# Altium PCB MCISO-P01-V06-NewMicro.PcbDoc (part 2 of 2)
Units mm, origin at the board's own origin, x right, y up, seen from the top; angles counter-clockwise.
Board outline 60 x 112.78 mm, 2 copper layers (Top Layer, Bottom Layer), stack 1.57 mm thick; 124 components, 85 nets, 520 pads, 108 vias.
Unrouted connection lines stored in the file: 6.
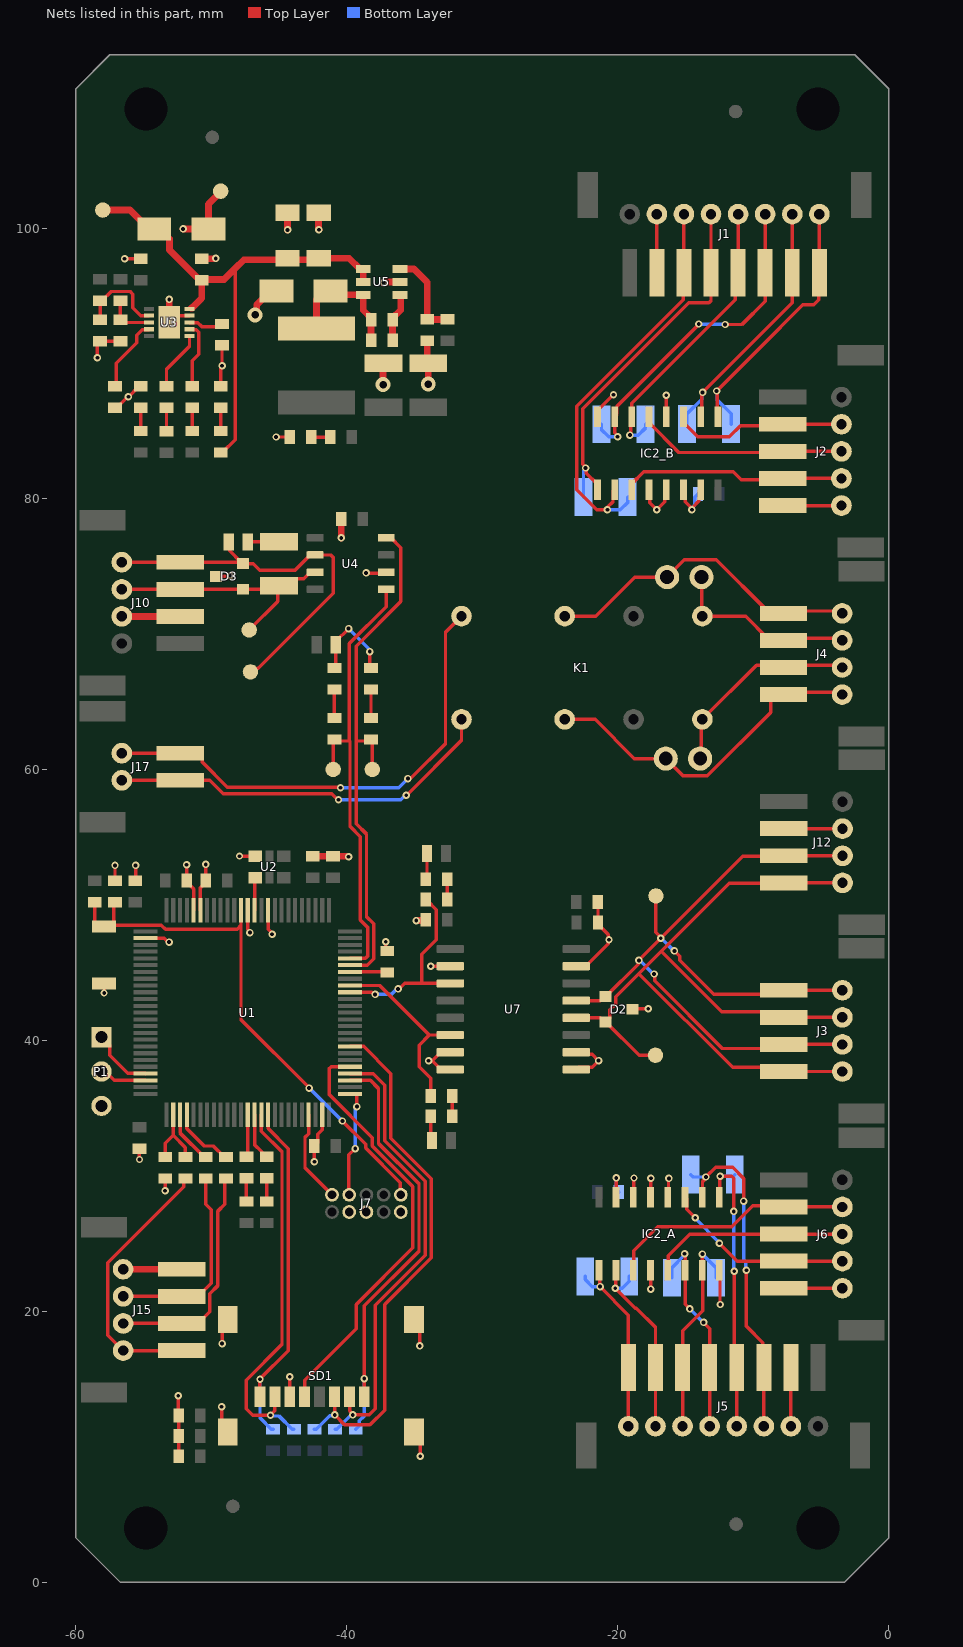
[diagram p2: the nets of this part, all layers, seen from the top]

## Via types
v1: diameter 0.55, hole 0.279, Top Layer to Bottom Layer, 100 vias
v2: diameter 1.1, hole 0.56, Top Layer to Bottom Layer, 3 vias
v3: diameter 0.508, hole 0.279, Top Layer to Bottom Layer, 3 vias
v4: diameter 1.092, hole 0.559, Top Layer to Bottom Layer, 2 vias

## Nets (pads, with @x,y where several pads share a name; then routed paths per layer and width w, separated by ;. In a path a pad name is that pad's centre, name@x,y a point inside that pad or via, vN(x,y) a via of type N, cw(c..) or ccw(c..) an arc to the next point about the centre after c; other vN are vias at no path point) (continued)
12VP: C11.2 C18.1 C21.1 D1.K R14.2 TP2.1 U3.10 U5.4 U5.5 | length 40.3
  Top Layer w0.254: U3.10@-51.611,94.026 U3.10@-51.517,94.026 ; R14.2@-49.311,83.426 -49.184,83.426 -48.239,84.371 -48.239,97.008
  Top Layer w0.5: TP2.1@-58.011,101.326 -56.011,101.326 -54.611,99.926 D1.K@-54.211,99.926 -53.811,99.926 -53.088,99.203 -53.088,98.383 -50.711,96.006 -50.711,94.808 -51.415,94.104 U3.10@-51.486,94.104 ; C11.2@-50.711,96.133 -50.652,96.192 -49.055,96.192 -48.239,97.008 -47.59,97.657 -42.188,97.657 C18.1@-42.079,97.765 -39.834,97.765 -39.035,96.967 U5.4@-38.785,96.967 U5.5@-38.785,96.017
BOOT: R1.1 U1.94 | length 2.8
  Top Layer w0.254: U1.94@-39.761,45.076 -37.054,45.076 R1.1@-37.011,45.033
"CAN GLV RX": R25.1 TP9.1 U1.95 U4.4 | length 39
  Top Layer w0.254: U1.95@-39.761,45.576 -38.48,45.576 -38.014,46.042 -38.014,48.63 -38.544,49.159 -38.544,55.259 -39.311,56.026 -39.311,62.126 ; TP9.1@-38.111,60.026 -38.111,62.133 R25.1@-38.211,62.233 -38.318,62.126 -39.311,62.126 ; U4.4@-37.086,77.131 -36.736,77.131 -36.011,76.406 -36.011,72.426 -39.311,69.126 -39.311,62.926 -39.311,62.126
"CAN GLX TX": R24.1 TP11.1 U1.96 U4.1 | length 33.5
  Top Layer w0.254: TP11.1@-41.011,60.026 -41.011,62.133 R24.1@-40.911,62.233 -40.804,62.126 -39.811,62.126 ; U1.96@-39.761,46.076 -39.738,46.099 -38.617,46.099 -38.468,46.248 -38.468,48.384 -38.998,48.913 -38.998,55.071 -39.765,55.838 -39.765,62.08 -39.811,62.126 ; U4.1@-37.086,73.321 -37.086,72.051 -39.811,69.326 -39.811,62.126
"CAN H": D3.2 J10.4 J14.1 TP8.1 U4.6 | length 29.4
  Top Layer w0.254: J10.4@-56.611,75.326 J10.4@-52.282,75.326 D3.2@-47.811,75.326 ; J14.1@-48.708,76.826 -48.653,76.771 -48.653,76.168 D3.2@-47.811,75.326 ; D3.2@-47.661,75.226 -46.911,75.226 -46.411,74.726 -43.821,74.726 -42.686,75.861 U4.6@-42.336,75.861 -41.195,75.861 -41.011,75.677 -41.011,73.026 -46.541,67.496 -46.601,67.496 -46.87,67.226 TP8.1@-47.111,67.226 ; D3.2@-47.661,75.326 D3.2@-47.811,75.326
"CAN HV RX": R22.1 U1.91 U7.3 | length 14.7
  Top Layer w0.254: U1.91@-39.761,43.576 -38.147,43.576 -37.991,43.42 v1(-37.911,43.42) ; v1(-36.211,43.826) -36.131,43.826 -35.726,44.231 -34.425,44.231 ; R22.1@-34.08,50.371 -33.393,49.684 -33.393,47.44 -34.454,46.379 -34.454,44.261 -34.425,44.231 ; U7.3@-32.361,44.231 -34.425,44.231
  Bottom Layer w0.254: v1(-37.911,43.42) -36.697,43.42 -36.291,43.826 v1(-36.211,43.826)
"CAN HV TX": R21.1 U1.92 U7.6 | length 14.1
  Top Layer w0.254: U1.92@-39.761,44.076 -37.561,44.076 -33.906,40.421 ; R21.1@-33.804,35.926 -33.804,37.221 -34.662,38.079 -34.662,39.665 -33.906,40.421 ; U7.6@-32.361,40.421 -33.906,40.421
"CAN L": D3.1 J10.3 R26.1 TP10.1 U4.7 | length 18.6
  Top Layer w0.254: J10.3@-56.611,73.326 J10.3@-52.282,73.326 -47.911,73.326 D3.1@-47.661,73.326 -45.036,73.326 -45.111,73.252 -45.111,72.426 TP10.1@-47.211,70.326 ; R26.1@-45.011,73.575 -44.488,74.098 -43.179,74.098 -42.686,74.591 U4.7@-42.336,74.591
"CAN MAIN LED": DS9.1 DS10.1 J13.2 | length 7
  Top Layer w0.254: DS9.1@-40.911,67.52 -40.814,67.617 J13.2@-40.814,69.226 -40.814,69.48 v1(-39.868,70.426) v1@-39.811,70.426 ; v1(-38.311,68.726) -38.311,67.62 DS10.1@-38.211,67.52
  Bottom Layer w0.254: v1(-39.868,70.426) -38.311,68.869 v1(-38.311,68.726)
"CAN MAIN RX LED": DS10.2 R25.2 | length 2.1
  Top Layer w0.254: R25.2@-38.211,63.82 DS10.2@-38.211,65.933
"CAN MAIN TX LED": DS9.2 R24.2 | length 2.1
  Top Layer w0.254: R24.2@-40.911,63.82 DS9.2@-40.911,65.933
"CAN RX LED": DS8.2 R22.2 | length 1.4
  Top Layer w0.254: R22.2@-32.586,50.423 -32.586,51.757 DS8.2@-32.518,51.826
"CAN TX LED": DS7.2 R21.2 | length 1.5
  Top Layer w0.254: DS7.2@-32.218,34.426 R21.2@-32.218,35.926
CLMODE: R15.2 U3.4 | length 5.6
  Top Layer w0.254: R15.2@-57.011,88.226 -57.011,90.019 -55.511,91.519 -55.511,92.082 -55.09,92.503 -54.634,92.503 U3.4@-54.611,92.526
"COM A": J4.4 J8.1 K1.13 | length 25.4
  Top Layer w0.254: K1.13@-23.911,63.726 -21.665,63.726 -18.765,60.826 J8.1@-16.451,60.826 -15.181,59.556 -13.385,59.556 -8.711,64.23 -8.711,65.303 -8.288,65.726 -7.74,65.726 J4.4@-3.411,65.726
"COM B": J4.1 J9.2 K1.4 | length 23.8
  Top Layer w0.254: K1.4@-23.911,71.346 -21.605,71.346 -18.725,74.226 J9.2@-16.351,74.226 -15.081,75.496 -12.71,75.496 -8.94,71.726 -7.74,71.726 J4.1@-3.411,71.726
FLAG: DS4.2 U3.6 | length 4.4
  Top Layer w0.254: DS4.2@-53.311,88.313 -53.311,89.559 -51.611,91.259 U3.6@-51.611,92.026
GND: C1.1 C2.1 C3.1 C4.1 C5.1 C6.2 C7.1 C8.1 C9.1 C10.1 C11.1 C12.1 C15.2 C18.2 C19.1 C21.2 C22.1 C23.1 C24.1 D1.A D3.3 D4.A DS5.2 DS6.2 DS11.2 J7.3 J7.5 J7.9 J10.2 J15.4 P1.3 R1.2 R8.1 R15.1 R16.1 R17.1 R18.1 R29.1 SD1.6 SD1.9 SD1.10 SD1.11 SD1.12 SW1.1 TP3.1 U1.10 U1.13 U1.20 U1.21 U1.27 U1.74 U2.3 U3.9 U3.11 U4.2 U5.2 U7.2 U7.7 U7.8 | length 89.3
  Top Layer w0.254: v1(-58.411,90.426) -58.411,91.439 R16.1@-58.211,91.639 R17.1@-56.711,91.639 ; v3(-57.911,43.526) SW1.1@-57.911,44.326 ; R15.1@-57.124,86.72 R15.1@-57.111,86.733 ; C7.1@-57.111,51.82 v1(-57.112,52.944) ; R15.1@-57.011,86.639 -57.011,86.706 -56.177,87.54 -56.111,87.54 -55.338,88.313 DS5.2@-55.211,88.313 ; v1(-56.405,97.737) -55.229,97.737 C12.1@-55.211,97.72 ; C3.1@-55.611,51.82 -55.59,51.84 v1(-55.59,52.942) ; v3(-55.311,31.226) C4.1@-55.311,32.033 ; U1.27@-54.861,47.576 -53.492,47.576 -53.198,47.282 v1(-53.118,47.282) ; v1(-53.411,28.926) R8.1@-53.411,29.826 ; U3.11@-53.111,93.026 -52.611,93.526 U3.9@-51.611,93.526 ; v1(-52.439,13.792) -52.439,12.348 C10.1@-52.417,12.326 C9.1@-52.417,10.826 C8.1@-52.417,9.326 ; v1(-51.824,52.984) -51.824,51.839 C5.1@-51.811,51.826 -51.811,51.699 -51.311,51.199 U1.21@-51.311,49.626 ; U1.20@-50.811,49.626 -50.803,49.634 -50.803,51.301 -50.404,51.699 C24.1@-50.404,51.826 -50.411,51.832 v1(-50.411,53.015) ; D3.3@-49.661,74.276 -48.674,74.276 -48.624,74.326 v1(-48.611,74.326) ; DS6.2@-49.311,88.313 -49.311,89.646 -49.211,89.746 R18.1@-49.211,91.333 ; v1(-49.241,12.984) -49.241,11.576 SD1.9@-48.791,11.126 ; v1(-49.204,17.637) -49.204,19.013 SD1.10@-48.791,19.426 ; v3(-47.911,53.626) U2.3@-46.761,53.626 ; U1.13@-47.311,49.626 -47.311,48.223 -47.155,48.067 v1(-47.155,47.986) ; U1.10@-45.811,49.626 -45.811,48.238 -45.517,47.944 v1(-45.517,47.864) ; v1(-45.22,84.571) -44.221,84.571 DS11.2@-44.212,84.562 ; v1(-44.212,15.192) -44.212,13.727 SD1.6@-44.211,13.726 ; v1(-42.392,31.065) -42.392,32.221 C1.1@-42.398,32.226 -42.144,32.48 -42.144,33.093 -41.82,33.417 -41.82,34.517 U1.74@-41.811,34.526 ; v1@-38.558,74.499 -37.178,74.499 U4.2@-37.086,74.591 ; v1(-37.128,47.309) -37.128,46.737 R1.2@-37.011,46.62 ; SD1.12@-35.041,11.126 -34.583,10.668 v1(-34.583,9.321) ; SD1.11@-35.041,19.426 -34.618,19.003 v1(-34.618,17.468) ; v1(-33.963,38.515) v1@-33.697,38.515 ; v1(-33.798,45.503) v1(-33.798,45.503) -32.362,45.502 U7.2@-32.361,45.501 ; U7.8@-32.361,37.881 -33.061,37.881 -33.695,38.515 v1@-33.697,38.515 ; U7.7@-32.361,39.151 -33.061,39.151 v1@-33.697,38.515
  Top Layer w0.5: J10.2@-56.611,71.326 J10.2@-52.282,71.326 ; J15.4@-56.511,23.126 J15.4@-52.182,23.126 ; U3.11@-53.111,93.026 v1(-53.111,94.726) ; v1(-52.088,99.929) -50.214,99.929 D1.A@-50.211,99.926 -50.211,101.757 -49.311,102.657 TP3.1@-49.311,102.726 ; C11.1@-50.711,97.72 -50.708,97.723 -49.724,97.723 -49.693,97.754 v1(-49.679,97.754) ; v2(-46.765,93.584) -46.651,93.699 -46.651,94.307 -45.599,95.358 D4.A@-45.199,95.358 ; C21.2@-44.379,101.122 -44.374,101.117 v1(-44.374,99.855) ; C6.2@-42.511,53.62 -39.924,53.62 -39.885,53.58 v1(-39.871,53.58) ; C18.2@-42.079,101.122 -42.079,99.9 -42.058,99.879 v1(-42.058,99.865) ; v1(-40.404,77.124) C15.2@-40.404,78.526 ; v2(-37.318,88.442) -37.318,89.994 C22.1@-37.303,90.009 ; v1(-37.284,95.968) -37.27,95.968 -37.222,96.017 U5.2@-36.085,96.017 ; v1(-34.871,48.865) -34.862,48.875 -34.222,48.875 C23.1@-34.173,48.923 ; R29.1@-34.066,91.669 -34.066,90.103 C19.1@-33.988,90.024 -33.984,90.02 v2(-33.984,88.47)
  other v1: -38.576,74.532 -56.125,87.54 -49.211,89.826
"GND INV A": C20_B.1 IC2_B.4 IC2_B.8 IC2_B.12 IC2_B.13 IC2_B.14 IC2_B.15 J1.2 J2.5 | length 20
  Top Layer w0.254: IC2_B.8@-21.52,86.498 -20.324,87.694 v1(-20.311,87.694) ; IC2_B.12@-17.71,80.673 -17.634,80.598 -17.634,79.724 v1(-17.109,79.198) -16.525,79.782 -16.525,80.588 IC2_B.13@-16.44,80.673 ; J1.2@-17.111,96.686 J1.2@-17.111,101.026 ; IC2_B.4@-16.44,86.073 -16.425,86.088 -16.425,87.632 v1(-16.41,87.647) ; IC2_B.14@-15.17,80.673 -15.022,80.525 -15.022,79.794 -14.58,79.353 -14.58,79.335 -14.542,79.296 -14.506,79.296 -14.467,79.335 -14.467,79.397 -13.998,79.866 -13.998,80.575 IC2_B.15@-13.9,80.673 ; J2.5@-7.828,79.511 J2.5@-3.499,79.511
  Bottom Layer w0.254: v1@-14.524,79.264 -14.524,79.344 -14.319,79.549 -14.319,80.114 C20_B.1@-14.065,80.368
  other v1: -14.524,79.198
"GND INV B": C13.1 C14.1 C20_A.1 D2.3 IC2_A.4 IC2_A.8 IC2_A.12 IC2_A.13 IC2_A.14 IC2_A.15 J5.2 J6.5 J12.2 U7.9 U7.10 U7.15 | length 35.2
  Top Layer w0.254: U7.9@-23.061,37.881 -22.888,38.054 -21.889,38.054 v1(-21.407,38.536) -21.436,38.536 -21.886,38.985 -22.895,38.985 U7.10@-23.061,39.151 ; U7.15@-23.061,45.501 -22.361,45.501 -20.697,47.165 -20.697,47.4 v1(-20.641,47.457) -20.697,47.513 -20.697,47.843 -21.452,48.598 -21.452,50.226 C14.1@-21.468,50.242 ; v1(-20.102,29.872) -20.096,29.867 -20.096,28.455 IC2_A.15@-20.09,28.449 ; D2.3@-18.911,42.326 -18.87,42.367 v1(-17.739,42.367) ; IC2_A.14@-18.82,28.449 -18.809,28.461 -18.809,29.851 v1(-18.797,29.863) ; v1(-17.556,21.661) -17.55,21.667 IC2_A.4@-17.55,23.049 ; IC2_A.13@-17.55,28.45 v1(-17.549,29.842) ; IC2_A.12@-16.28,28.449 -16.249,28.48 -16.249,29.801 v1(-16.218,29.832) ; IC2_A.8@-12.47,23.049 -12.448,23.026 -12.448,20.55 v1(-12.425,20.527) ; J6.5@-7.74,21.726 J6.5@-3.411,21.726 ; J12.2@-7.73,55.653 J12.2@-3.401,55.653 ; J5.2@-7.211,11.536 J5.2@-7.211,15.876
  Bottom Layer w0.254: v1(-20.102,29.872) -20.102,28.996 C20_A.1@-19.932,28.826
H1_A: IC2_A.3 J6.2 | length 18.3
  Top Layer w0.254: IC2_A.3@-18.82,23.049 -18.82,24.493 -17.043,26.271 -11.576,26.271 -10.023,27.823 -7.837,27.823 J6.2@-7.74,27.726 J6.2@-3.411,27.726
H1_B: IC2_B.3 J2.2 | length 13
  Top Layer w0.254: IC2_B.3@-15.17,86.073 -15.17,85.648 -14.1,84.578 -11.764,84.578 -10.936,85.406 -7.781,85.406 J2.2@-7.761,85.426 ; J2.2@-7.828,85.511 J2.2@-3.499,85.511
H2_A: IC2_A.5 J6.3 | length 14.6
  Top Layer w0.254: IC2_A.5@-16.28,23.049 -16.28,24.135 -14.689,25.726 J6.3@-7.74,25.726 J6.3@-3.411,25.726
H2_B: IC2_B.5 J2.3 | length 15.6
  Top Layer w0.254: IC2_B.5@-17.71,86.073 -17.71,85.648 -15.487,83.426 J2.3@-7.761,83.426 ; J2.3@-7.828,83.511 J2.3@-3.499,83.511
H3_A: IC2_A.11 J6.4 | length 14.1
  Top Layer w0.254: IC2_A.11@-15.01,28.449 -14.912,28.351 -14.912,27.56 -14.279,26.927 v1(-14.275,26.927) ; v1(-12.491,25.053) -11.164,23.726 J6.4@-3.411,23.726
  Bottom Layer w0.254: v1(-14.275,26.927) -14.275,26.882 -12.491,25.097 v1(-12.491,25.053)
H3_B: IC2_B.11 J2.4 | length 16.6
  Top Layer w0.254: IC2_B.11@-18.98,80.673 -18.98,81.098 -18.064,82.014 -11.468,82.014 -10.88,81.426 J2.4@-7.761,81.426 ; J2.4@-7.828,81.511 J2.4@-3.499,81.511
"HALL 1A_A": IC2_A.2 J5.7 R19_A.1 | length 14.4
  Top Layer w0.254: IC2_A.2@-20.133,23.007 -20.145,22.995 -20.145,21.754 v1(-20.174,21.725) -18.707,20.258 -18.621,20.258 -17.211,18.848 J5.7@-17.211,15.876 J5.7@-17.211,11.536
  Bottom Layer w0.254: v1(-20.174,21.725) -19.674,21.725 -19.151,22.248 R19_A.1@-19.151,22.599
"HALL 1A_B": IC2_B.2 J1.7 R19_B.1 | length 20.6
  Top Layer w0.254: IC2_B.2@-13.9,86.073 -13.79,86.182 -13.79,87.805 -7.111,94.485 J1.7@-7.111,96.686 J1.7@-7.111,101.026
  Bottom Layer w0.254: R19_B.1@-14.882,85.522 -14.882,86.272 -13.79,87.364 -13.79,87.805 v1(-13.734,87.862)
"HALL 1B_A": IC2_A.1 J5.8 R19_A.2 | length 13.9
  Top Layer w0.254: IC2_A.1@-21.36,23.049 -21.33,23.019 -21.33,21.881 v1(-21.3,21.851) -21.3,21.824 -19.211,19.735 J5.8@-19.211,15.876 J5.8@-19.211,11.536
  Bottom Layer w0.254: R19_A.2@-22.402,22.599 -22.402,22.374 -21.879,21.851 v1(-21.3,21.851)
"HALL 1B_B": IC2_B.1 J1.8 R19_B.2 | length 21.5
  Top Layer w0.254: IC2_B.1@-12.63,86.073 -12.653,86.096 -12.653,87.919 -12.701,87.968 v1(-12.701,87.967) -9.564,91.104 -6.338,94.33 -5.532,94.33 -5.158,94.704 -5.158,96.64 J1.8@-5.111,96.686 J1.8@-5.111,101.026
  Bottom Layer w0.254: v1(-12.701,87.967) -12.67,87.936 -12.67,87.311 -11.631,86.272 R19_B.2@-11.631,85.522
"HALL 2A_A": IC2_A.6 J5.5 R20_A.1 | length 15.6
  Top Layer w0.254: v1@-15.021,24.249 -15.01,24.238 -15.01,23.049 -15.01,20.538 -14.684,20.212 v1(-14.684,20.2) ; v1(-13.657,19.199) -13.657,19.193 -13.196,18.732 -13.196,15.891 J5.5@-13.211,15.876 J5.5@-13.211,11.536
  Bottom Layer w0.254: R20_A.1@-15.992,22.499 -15.992,23.249 -15.118,24.123 -15.118,24.216 v1(-15.061,24.273) ; v1(-14.684,20.2) -14.671,20.2 -13.67,19.199 v1(-13.657,19.199)
"HALL 2A_B": IC2_B.6 J1.5 R20_B.1 | length 21.3
  Top Layer w0.254: v1(-19.095,84.713) -19.038,84.769 -19.038,86.015 -18.954,86.099 -18.954,87.056 -11.306,94.704 -11.306,96.491 J1.5@-11.111,96.686 J1.5@-11.111,101.026
  Bottom Layer w0.254: v1(-19.095,84.713) -18.468,84.713 -17.945,85.236 R20_B.1@-17.945,85.513
"HALL 2B_A": IC2_A.7 J5.6 R20_A.2 | length 15.5
  Top Layer w0.254: J5.6@-15.211,11.536 J5.6@-15.211,15.876 -15.211,18.573 -13.707,20.077 -13.707,23.016 -13.74,23.049 -13.755,23.064 v1@-13.755,24.233
  Bottom Layer w0.254: v1(-13.747,24.249) -13.741,24.249 -12.741,23.249 R20_A.2@-12.741,22.499
"HALL 2B_B": IC2_B.7 J1.6 R20_B.2 | length 24.9
  Top Layer w0.254: v1(-20.006,84.585) -20.006,84.665 -20.225,84.884 -20.225,86.048 -20.25,86.073 -20.052,86.271 -20.052,86.847 -14.023,92.875 v1(-14.023,92.914) ; v1(-12.075,92.877) -10.824,92.877 -9.111,94.59 J1.6@-9.111,96.686 J1.6@-9.111,101.026
  Bottom Layer w0.254: R20_B.2@-21.196,85.513 -21.196,85.108 -20.673,84.585 v1(-20.006,84.585) ; v1(-14.023,92.914) -14.004,92.896 -12.094,92.896 v1(-12.075,92.877)
"HALL 3A_A": IC2_A.10 J5.3 R23_A.1 | length 25.2
  Top Layer w0.254: IC2_A.10@-13.74,28.449 -13.74,29.606 -13.496,29.851 v1@-13.496,29.939 ; v1(-13.487,29.939) -12.774,30.652 -11.521,30.652 -10.697,29.828 v1@-10.697,28.136 ; v1(-10.493,23.047) -10.493,18.925 -9.284,17.716 -9.284,15.949 J5.3@-9.211,15.876 J5.3@-9.211,11.536
  Bottom Layer w0.254: R23_A.1@-14.616,30.119 -14.437,29.939 v1(-13.487,29.939) ; v1(-10.708,28.159) -10.708,23.83 -10.55,23.672 -10.55,23.104 v1(-10.493,23.047)
"HALL 3A_B": IC2_B.10 J1.3 R23_B.1 | length 30.2
  Top Layer w0.254: v1(-20.762,79.198) -20.771,79.19 -21.542,79.19 -23.023,80.671 -23.023,86.848 -15.167,94.704 -15.167,96.63 J1.3@-15.111,96.686 J1.3@-15.111,101.026 ; v1@-20.762,79.369 -20.348,79.784 -20.348,80.575 IC2_B.10@-20.25,80.673
  Bottom Layer w0.254: v1(-20.762,79.198) -20.75,79.186 -19.796,79.186 -19.273,79.709 R23_B.1@-19.273,80.136
"HALL 3B_A": IC2_A.9 J5.4 R23_A.2 | length 22.1
  Top Layer w0.254: IC2_A.9@-12.47,28.449 -12.467,28.453 v1@-12.467,29.796 ; v1@-12.442,29.796 v1(-12.442,29.996) -11.587,29.996 -11.438,29.847 v1(-11.438,27.395) ; v1(-11.393,22.978) -11.393,16.058 J5.4@-11.211,15.876 J5.4@-11.211,11.536
  Bottom Layer w0.254: v1(-12.442,29.996) -11.489,29.996 R23_A.2@-11.366,30.119 ; v1(-11.438,27.395) -11.416,27.372 -11.416,23.001 v1(-11.393,22.978)
"HALL 3B_B": IC2_B.9 J1.4 R23_B.2 | length 27.8
  Top Layer w0.254: v1@-22.369,82.284 -22.312,82.227 -22.312,81.891 -21.52,81.098 IC2_B.9@-21.52,80.673 ; v1(-22.367,82.284) -22.367,82.364 -22.569,82.566 -22.569,86.66 -14.75,94.478 -13.26,94.478 -13.111,94.627 J1.4@-13.111,101.026
  Bottom Layer w0.254: R23_B.2@-22.524,80.136 -22.524,82.049 -22.367,82.206 v1(-22.367,82.284)
"ISO CAN H": D2.1 J3.1 J3.3 J12.3 TP6.1 U7.13 | length 61.7
  Top Layer w0.254: U7.13@-23.061,42.961 -21.276,42.961 -20.961,43.276 -20.861,43.276 -18.49,45.647 -18.49,45.869 v1(-18.433,45.925) -18.433,45.942 -16.822,47.553 v1(-16.822,47.57) ; v1(-17.311,44.926) -17.254,44.869 -17.254,44.412 -12.269,39.426 -8.061,39.426 -7.761,39.726 J3.3@-3.432,39.726 ; TP6.1@-17.175,50.686 -17.175,48.003 -16.822,47.65 v1(-16.822,47.57) ; v1(-15.811,46.626) -15.411,46.226 -15.411,45.926 -12.911,43.426 -8.061,43.426 -7.761,43.726 J3.1@-3.432,43.726 ; J12.3@-7.73,53.653 -7.048,53.653 J12.3@-3.401,53.653 ; J12.3@-7.048,53.61 -10.781,53.61 v1(-16.822,47.57)
  Bottom Layer w0.254: v1(-18.433,45.925) -18.371,45.925 -17.372,44.926 v1(-17.311,44.926) ; v1(-16.822,47.57) -16.788,47.57 -15.845,46.626 v1(-15.811,46.626)
"ISO CAN L": D2.2 J3.2 J3.4 J12.4 TP4.1 U7.12 | length 62.8
  Top Layer w0.254: U7.12@-23.061,41.691 -21.276,41.691 -20.961,41.376 D2.2@-20.911,41.376 D2.2@-20.861,41.376 ; TP4.1@-17.211,38.926 -18.411,38.926 D2.2@-20.861,41.376 ; J3.4@-3.432,37.726 -7.761,37.726 -8.061,38.026 -11.511,38.026 -18.44,44.955 ; J3.2@-3.432,41.726 -7.761,41.726 -8.161,42.126 -12.311,42.126 -16.79,46.605 ; J12.4@-3.401,51.653 J12.4@-7.73,51.653 -7.751,51.632 -11.763,51.632 -16.79,46.605 ; D2.2@-20.861,41.376 -20.588,41.649 -20.588,42.272 -20.156,42.704 -20.156,43.239 -18.44,44.955 ; -18.44,44.955 -16.79,46.605
NetDS1_1: DS1.1 R3.1 | length 1.7
  Top Layer w0.254: R3.1@-45.911,28.131 DS1.1@-45.911,29.839
NetDS2_1: DS2.1 R4.1 | length 1.7
  Top Layer w0.254: R4.1@-47.411,28.131 DS2.1@-47.411,29.839
NetDS3_1: DS3.1 R9.1 | length 1.7
  Top Layer w0.254: R9.1@-51.411,85.013 DS3.1@-51.411,86.72
NetDS4_1: DS4.1 R10.1 | length 1.7
  Top Layer w0.254: R10.1@-53.311,85.006 DS4.1@-53.311,86.726
NetDS5_1: DS5.1 R11.1 | length 1.7
  Top Layer w0.254: R11.1@-55.211,85.013 DS5.1@-55.211,86.726
NetDS6_1: DS6.1 R14.1 | length 1.7
  Top Layer w0.254: R14.1@-49.311,85.013 DS6.1@-49.311,86.726
NetDS7_1: DS7.1 J11.2 | length 1.8
  Top Layer w0.254: DS7.1@-33.804,34.426 -33.804,32.723 J11.2@-33.708,32.626
NetDS8_1: DS8.1 J16.1 | length 1.9
  Top Layer w0.254: DS8.1@-34.173,51.923 -34.077,52.02 J16.1@-34.077,53.823
NetDS11_1: DS11.1 R28.1 | length 1.4
  Top Layer w0.254: DS11.1@-42.625,84.562 R28.1@-41.212,84.562
NetJ14_2: J14.2 R26.2 | length 2.3
  Top Layer w0.254: J14.2@-47.311,76.826 R26.2@-45.011,76.826
"NO COM A": J4.3 J8.2 K1.9 | length 15
  Top Layer w0.254: J8.2@-13.911,60.826 -13.831,60.906 -13.831,63.646 K1.9@-13.751,63.726 -9.751,67.726 J4.3@-3.411,67.726
"NO COM B": J4.2 J9.1 K1.8 | length 13.9
  Top Layer w0.254: J9.1@-13.811,74.226 -13.781,74.196 -13.781,71.376 K1.8@-13.751,71.346 -10.56,71.346 -8.94,69.726 -7.74,69.726 J4.2@-3.411,69.726
NRST: C7.2 J7.10 R2.1 SW1.2 U1.14 | length 40.1
  Top Layer w0.254: R2.1@-58.484,50.233 R2.1@-58.611,50.233 -58.611,48.744 -58.293,48.426 SW1.2@-57.911,48.426 ; SW1.2@-57.911,48.326 -57.811,48.426 -57.466,48.426 SW1.2@-57.362,48.531 ; C7.2@-57.111,50.233 -57.211,50.133 -57.211,48.682 SW1.2@-57.362,48.531 ; -47.811,48.503 -48.097,48.217 -53.383,48.217 -53.697,48.531 SW1.2@-57.362,48.531 ; U1.14@-47.811,49.162 -47.811,48.421 -47.811,41.545 -42.781,36.515 v1(-42.781,36.507) ; v1(-40.324,34.073) -38.611,32.359 -38.611,32.079 -36.047,29.515 -36.047,28.662 J7.10@-36.011,28.626
  Bottom Layer w0.254: v1(-42.781,36.507) -42.758,36.507 v1(-40.324,34.073)
"ORANGE LED 1": DS1.2 U1.64 | length 3.5
  Top Layer w0.254: U1.64@-46.811,34.526 -46.811,32.326 -46.292,31.807 -46.292,31.68 -46.038,31.426 DS1.2@-45.911,31.426
"ORANGE LED 2": DS2.2 U1.63 | length 3.1
  Top Layer w0.254: DS2.2@-47.411,31.426 -47.311,31.526 U1.63@-47.311,34.526
"OSC IN": U1.12 U2.4 | length 2.4
  Top Layer w0.254: U1.12@-46.811,49.626 -46.811,51.976 U2.4@-46.761,52.026
OVLO: R13.1 R17.2 U3.3 | length 3.6
  Top Layer w0.254: R13.1@-56.711,94.626 R17.2@-56.711,93.226 -56.511,93.026 U3.3@-54.611,93.026
"PWR CB 3V3": C16.1 C17.1 U5.1 | length 3.6
  Top Layer w0.5: C17.1@-36.618,91.711 C16.1@-36.618,93.222 -36.618,93.349 -36.015,93.952 -36.015,95.017 -36.065,95.067 U5.1@-36.085,95.067
"PWR FB 3V3": R27.1 R29.2 U5.3 | length 6.7
  Top Layer w0.5: U5.3@-36.085,96.967 -35.03,96.967 -34.066,96.003 R29.2@-34.066,93.255 R27.1@-32.566,93.255
"PWR SW 3V3": C16.2 C17.2 D4.K L1.1 U5.6 | length 9.6
  Top Layer w0.5: L1.1@-42.244,92.577 -42.244,94.713 -41.599,95.358 D4.K@-41.199,95.358 -40.908,95.067 U5.6@-38.785,95.067 -38.785,93.928 -38.205,93.349 C16.2@-38.205,93.222 C17.2@-38.205,91.711
SD_CMD: R32.1 SD1.3 U1.83 | length 39.1
  Top Layer w0.254: SD1.3@-40.911,13.726 -40.891,13.706 v1(-40.891,12.373) -40.171,11.653 -38.285,11.653 -37.211,12.726 -37.211,20.526 -33.76,23.977 -33.76,29.801 -36.749,32.79 -36.749,37.564 -38.761,39.576 U1.83@-39.761,39.576
  Bottom Layer w0.254: R32.1@-42.388,11.317 -42.261,11.317 -41.263,12.316 -40.948,12.316 v1(-40.891,12.373)
SD_D0: R31.1 SD1.7 U1.65 | length 29.1
  Top Layer w0.254: U1.65@-46.311,34.526 -46.311,33.321 -44.782,31.792 -44.782,17.575 -47.411,14.946 -47.411,12.826 -46.933,12.349 v1(-45.632,12.349) -45.311,12.67 SD1.7@-45.311,13.726
  Bottom Layer w0.254: v1(-45.632,12.349) -45.575,12.292 -45.008,12.292 -44.033,11.317 R31.1@-43.906,11.317
SD_D1: R30.1 SD1.8 U1.66 | length 26.5
  Top Layer w0.254: SD1.8@-46.411,13.726 -46.411,15.026 -44.311,17.126 -44.311,32.026 -45.802,33.517 -45.802,34.517 U1.66@-45.811,34.526
  Bottom Layer w0.254: v1(-46.406,15.009) -46.406,12.156 -45.568,11.317 R30.1@-45.441,11.317
SD_D2: R34.1 SD1.1 U1.78 | length 32
  Top Layer w0.254: U1.78@-39.761,37.076 -39.752,37.067 -38.252,37.067 -37.657,36.472 -37.657,32.414 -34.668,29.425 -34.668,24.469 -38.711,20.426 SD1.1@-38.711,13.726
  Bottom Layer w0.254: R34.1@-39.337,11.317 -39.333,11.317 -39.079,11.571 -39.079,11.931 -38.715,12.294 v1(-38.715,15.055)
SD_D3: R33.1 SD1.2 U1.79 | length 34.6
  Top Layer w0.254: SD1.2@-39.811,13.726 -39.785,13.7 -39.785,12.662 -39.561,12.438 v1(-39.561,12.376) -38.355,12.376 -37.911,12.82 -37.911,20.468 -34.214,24.165 -34.214,29.613 -37.203,32.602 -37.203,36.718 -38.052,37.567 -39.752,37.567 U1.79@-39.761,37.576
  Bottom Layer w0.254: R33.1@-40.862,11.317 -40.735,11.317 -39.733,12.319 -39.618,12.319 v1(-39.561,12.376)
SDIO_CK: SD1.5 U1.80 | length 31.7
  Top Layer w0.254: SD1.5@-43.111,13.726 -43.111,14.926 -39.311,18.726 -39.311,20.526 -35.122,24.715 -35.122,29.237 -38.111,32.226 -38.111,32.849 -41.311,36.049 -41.311,37.926 -41.161,38.076 U1.80@-39.761,38.076
SETI: R18.2 U3.8 | length 2.6
  Top Layer w0.254: U3.8@-51.611,93.026 -51.588,93.003 -50.988,93.003 -50.711,92.726 -49.404,92.726 R18.2@-49.211,92.92
SHDN_CHAIN_IN: J17.2 K1.1 | length 36.3
  Top Layer w0.254: J17.2@-56.611,61.226 -51.082,61.226 -50.659,60.803 -50.659,60.574 -48.811,58.726 -40.518,58.726 v1(-40.465,58.673) ; v1(-35.489,59.352) -35.432,59.409 -35.228,59.409 -32.711,61.926 -32.711,70.166 K1.1@-31.531,71.346
  Bottom Layer w0.254: v1(-40.465,58.673) -36.169,58.673 v1(-35.489,59.352)
SHDN_CHAIN_OUT: J17.1 K1.16 | length 29
  Top Layer w0.254: J17.1@-56.611,59.226 J17.1@-52.282,59.226 -50.111,59.226 -49.111,58.226 -41.102,58.226 -40.664,57.788 v1(-40.613,57.788) ; v1(-35.611,58.126) -35.583,58.126 -31.531,62.178 K1.16@-31.531,63.726
  Bottom Layer w0.254: v1(-40.613,57.788) -36.029,57.788 -35.691,58.126 v1(-35.611,58.126)
SWCLK: J7.4 U1.76 | length 8.2
  Top Layer w0.254: J7.4@-39.821,28.626 -39.848,28.653 -39.848,31.567 v1(-39.377,32.038) ; U1.76@-39.761,36.076 -39.273,36.076 -39.251,36.055 v1(-39.251,35.141)
  Bottom Layer w0.254: v1(-39.377,32.038) -39.377,34.935 -39.251,35.061 v1(-39.251,35.141)
SWDIO: J7.2 U1.72 | length 6.8
  Top Layer w0.254: U1.72@-42.811,34.526 -42.811,33.133 -43.084,32.86 -43.084,30.619 J7.2@-41.091,28.626
USART3_RX: P1.2 U1.48 | length 3.5
  Top Layer w0.254: P1.2@-58.111,37.726 -57.811,37.726 -57.161,37.076 U1.48@-54.861,37.076
USART3_TX: P1.1 U1.47 | length 4.8
  Top Layer w0.254: P1.1@-58.111,40.266 -57.512,39.667 -57.512,38.927 -56.17,37.585 -54.87,37.585 U1.47@-54.861,37.576
"USB DM": R6.2 U1.53 | length 4
  Top Layer w0.254: U1.53@-52.311,34.526 -52.311,33.186 -50.538,31.413 R6.2@-50.411,31.413
"USB DP": R5.2 U1.54 | length 4.8
  Top Layer w0.254: U1.54@-51.811,34.526 -51.802,34.517 -51.802,33.517 -50.511,32.226 -49.845,32.226 -49.038,31.42 R5.2@-48.911,31.42
"USB M": J15.3 R6.1 | length 14.8
  Top Layer w0.254: J15.3@-56.511,21.126 J15.3@-52.182,21.126 -50.982,21.126 -50.011,22.097 -50.011,27.526 -50.411,27.926 R6.1@-50.411,29.826
"USB P": J15.2 R5.1 | length 17.1
  Top Layer w0.254: J15.2@-56.511,19.126 J15.2@-52.182,19.126 -50.982,19.126 -50.111,19.997 -50.111,21.326 -49.511,21.926 -49.511,27.426 -49.011,27.926 -49.011,29.733 R5.1@-48.911,29.833
USB_D6: R7.1 R8.2 U1.52 | length 5.3
  Top Layer w0.254: R8.2@-53.411,31.413 -53.411,32.415 -52.811,33.015 ; U1.52@-52.811,34.526 -52.811,33.015 ; R7.1@-51.911,31.42 -51.911,32.115 -52.811,33.015
UVLO: R12.1 R16.2 U3.2 | length 6.6
  Top Layer w0.254: R16.2@-58.211,93.226 R12.1@-58.211,94.626 -58.084,94.626 -57.398,95.312 -55.997,95.312 -55.788,95.103 -55.788,94.103 -55.211,93.526 U3.2@-54.611,93.526
UVOV: DS3.2 U3.7 | length 5
  Top Layer w0.254: U3.7@-51.611,92.526 -51.386,92.526 -51.341,92.481 -51.11,92.481 -50.931,92.302 -50.931,90.671 -51.411,90.191 DS3.2@-51.411,88.306
VUSB: J15.1 R7.2 | length 19.9
  Top Layer w0.254: J15.1@-52.182,17.126 J15.1@-56.511,17.126 -57.654,18.269 -57.654,23.6 -52.034,29.22 -52.034,29.71 R7.2@-51.911,29.833
pads on no net: FID1.1 FID2.1 FID3.1 FID4.1 J1.M J2.M J3.M J4.M J5.M J6.M J7.6 J7.7 J7.8 J10.M J12.M J15.M J17.M K1.6 K1.11 M1.1 M2.1 M3.1 M4.1 U1.1 U1.2 U1.3 U1.4 U1.5 U1.7 U1.8 U1.9 U1.15 U1.16 U1.17 U1.18 U1.23 U1.24 U1.25 U1.26 U1.29 U1.30 U1.31 U1.32 U1.33 U1.34 U1.35 U1.36 U1.37 U1.38 U1.39 U1.40 U1.41 U1.42 U1.43 U1.44 U1.45 U1.46 U1.49 U1.51 U1.55 U1.56 U1.57 U1.58 U1.59 U1.60 U1.61 U1.62 U1.67 U1.68 U1.69 U1.70 U1.71 U1.73 U1.77 U1.81 U1.82 U1.84 U1.85 U1.86 U1.87 U1.88 U1.89 U1.90 U1.93 U1.97 U1.98 U1.99 U2.2 U2.5 U3.5 U4.5 U4.8 U7.4 U7.5 U7.11 U7.14
copper on no net: | length 14
  Bottom Layer w0.254: -6.827,0 2.795,0 ; 0,-0.849 0,3.533

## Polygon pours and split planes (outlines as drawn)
no net on Bottom Overlay (solid): -36.29,23.642 -42.64,23.642 -42.64,56.662 -36.29,56.662
no net on Bottom Overlay (solid): -43.715,23.642 -50.065,23.642 -50.065,56.662 -43.715,56.662
"GND INV B" on Bottom Layer "GND_INV_B_L02_P060" (solid, pour order 60): -0.002,59.375 -0.14,59.237 -24.119,59.237 -24.119,8.065 -24.188,7.996 -0.036,7.996
"GND INV A" on Bottom Layer "GND_INV_A_L02_P061" (solid, pour order 61): -24.124,105.055 -24.092,105.022 0.011,105.022 0.011,75.595 -0.054,75.53 -0.087,75.563 -24.124,75.563
GND on Bottom Layer "GNDP" (solid, pour order 58): -59.812,110.287 -31.404,110.287 -31.404,7.882 -59.782,7.882

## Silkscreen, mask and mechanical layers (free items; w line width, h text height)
Top Overlay:
  lines w0.254: -47.911,79.426 -30.841,79.426 -30.841,104.126 -47.911,104.126 ; -47.911,79.426 -47.911,104.126 ; -47.911,79.426 -59.811,79.426 -59.811,104.126 -47.911,104.126 ; -47.911,79.426 -47.911,104.126 ; -50.511,57.15 -30.633,57.15 -30.633,79.426 -50.511,79.426 -50.511,57.15 ; -38.084,31.41 -30.829,31.41 -30.829,57.155 -38.084,57.155 -38.084,31.41
  lines w0.635: -24.341,68.726 -0.311,68.726
  lines w0.889: -30.911,0.074 -30.911,112.848 ; -24.613,0.036 -24.509,112.848
  text "GND" at -53.224,103.04 h1.54
  text "3V3" at -47.672,103.036 h1.54
  text "12VP" at -59.111,103.026 h1.54
  text "HV" at -25.265,96.38 h1.52 r90
  text "GLV" at -28.465,95.98 h1.52 r90
  text "Hall Pairs" at -15.411,93.441 h1.5
  text "Halls" at -10.896,85.326 h1.5 r270
  text "ISO 6.4mm" at -27.043,79.651 h1.52 r90
  text "SW / OVERRIDE" at -24.896,73.087 h1.3
  text "CAN_L" at -45.575,71.845 h1.54 r270
  text "INV   SWITCH" at -10.795,71.526 h1.5 r270
  text "CAN_H" at -45.575,67.245 h1.54 r270
  text "CAN ETHERNET  / BRIDGE" at -12.511,62.125 h1.5 r270
  text "TX" at -43.51,59.827 h1.54 r45
  text "SW / OVERRIDE" at -24.967,59.792 h1.3
  text "RX" at -36.211,59.626 h1.54 r45
  text "CAN H" at -18.895,53.484 h0.8
  text "CAN RX" at -34.165,43.48 h0.8 r90
  text "CAN" at -11.195,42.026 h1.5 r270
  text "CAN TX" at -34.365,37.18 h0.8 r90
  text "CAN L" at -18.557,36.58 h0.8
  text "HALLS" at -10.895,27.326 h1.5 r270
  text "HALL PAIRS" at -16.545,17.805 h1.5
  text "ISO 6.4mm" at -26.965,15.08 h1.52 r90
Bottom Overlay:
  text "Designed By: / John Hatfield / Bishwam Pattnaik" at -50.315,64.804 h3 r270
  text "MCISO V00" at -34.57,32.526 h3.81 r270
  text "Var." at -48.121,15.146 h5.08 r270
  text "S/N" at -40.614,15.142 h5.08 r270
Mechanical 1:
  the board outline again, w0.013

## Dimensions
-54.834,4.027 to -59.465,0.032 on Top Layer
-57.493,112.787 to -1.661,1.715 on Top Layer
-54.834,1.233 to -59.993,3.287 on Top Layer
-5.216,108.791 to -57.493,112.787 on Top Layer
-5.216,108.791 to -57.493,112.787 on Top Layer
